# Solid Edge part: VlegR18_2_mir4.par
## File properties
Author: Türk
Template: Iso Part.par
Last saved by: Türk
Revision: 4
Application: Solid Edge
Accuracy: 0,990
Username: Türk
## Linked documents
VlegR18_2.par
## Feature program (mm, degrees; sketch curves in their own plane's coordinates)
part copy "CopiedPart_1"
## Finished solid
Body 1: solid body, 154 faces, 385 edges, 214 vertices, 2 internal voids.
  Faces by surface: cylinder 72, torus 31, plane 24, blend 14, cone 8, spun 5
  Edges by curve: circle 176, intersection 113, line 96
Bounding box of the edges (mm; curved faces can reach further): 200.000 x 457.200 x 457.200, from (-100, -228.6, -228.6) to (100, 228.6, 228.6).
Cylindrical faces by radius (mm): R4 x16, R6 x5, R15 x5, R25 x16, R80 x8, R150 x8, R174.2298 x8, R203.6 x2, R216.1 x2, R228.6 x2
Conical faces (half-angle, radius in mm at the cone's reference point): 2.0106 deg R178.4522 x2, 5.4632 deg R201.6202 x2, 54.824 deg R174.2298 x1, 54.824 deg R203.0605 x2, 54.824 deg R203.6 x1
Toroidal faces (ring radius, tube radius in mm): R79 r1 x7, R136.945 r40 x8, R170 r20 x8, R205.6 r2 x2, R214.1 r2 x2, R226.6 r2 x4
Planar faces by outward normal: +x 4, -x 4, oblique 16
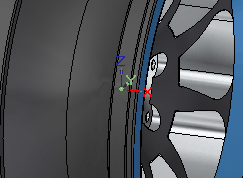
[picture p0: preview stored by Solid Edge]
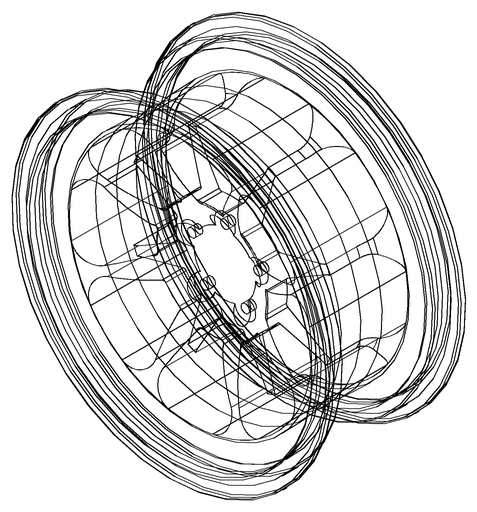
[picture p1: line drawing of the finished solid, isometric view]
